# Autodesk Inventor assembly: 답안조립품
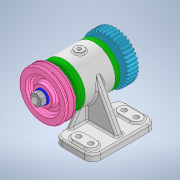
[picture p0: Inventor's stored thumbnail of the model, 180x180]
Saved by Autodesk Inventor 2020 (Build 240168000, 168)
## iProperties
Created: 2023-08
Part Number: 답안조립품
Document SubType Name: Assembly
Designer: oem
Author: oem
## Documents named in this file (12)
- C:\Users\oem\Desktop\730806V1006\답안조립품.iam
- C:\Users\oem\Desktop\730806V1006\본체.ipt
- C:\Users\oem\Desktop\730806V1006\축.ipt
- C:\Users\oem\Desktop\730806V1006\베어링 6204.ipt
- C:\Users\oem\Desktop\730806V1006\커버.ipt
- C:\Users\oem\Desktop\730806V1006\오일실 20x35x8.ipt
- C:\Users\oem\Desktop\730806V1006\키 5x5.ipt
- C:\Users\oem\Desktop\730806V1006\V벨트풀리.ipt
- C:\Users\oem\Desktop\730806V1006\와셔 12x24.ipt
- C:\Users\oem\Desktop\730806V1006\너트 M12x1.25.ipt
- C:\Users\oem\Desktop\730806V1006\볼트 M4 x 12.ipt
- C:\Users\oem\Desktop\730806V1006\스퍼기어.ipt
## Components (1 placed, 1 different names)
1. V벨트풀리:1 — 각도:3
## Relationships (1: Angle 1)
- 각도:3 [Angle]: V벨트풀리:1
